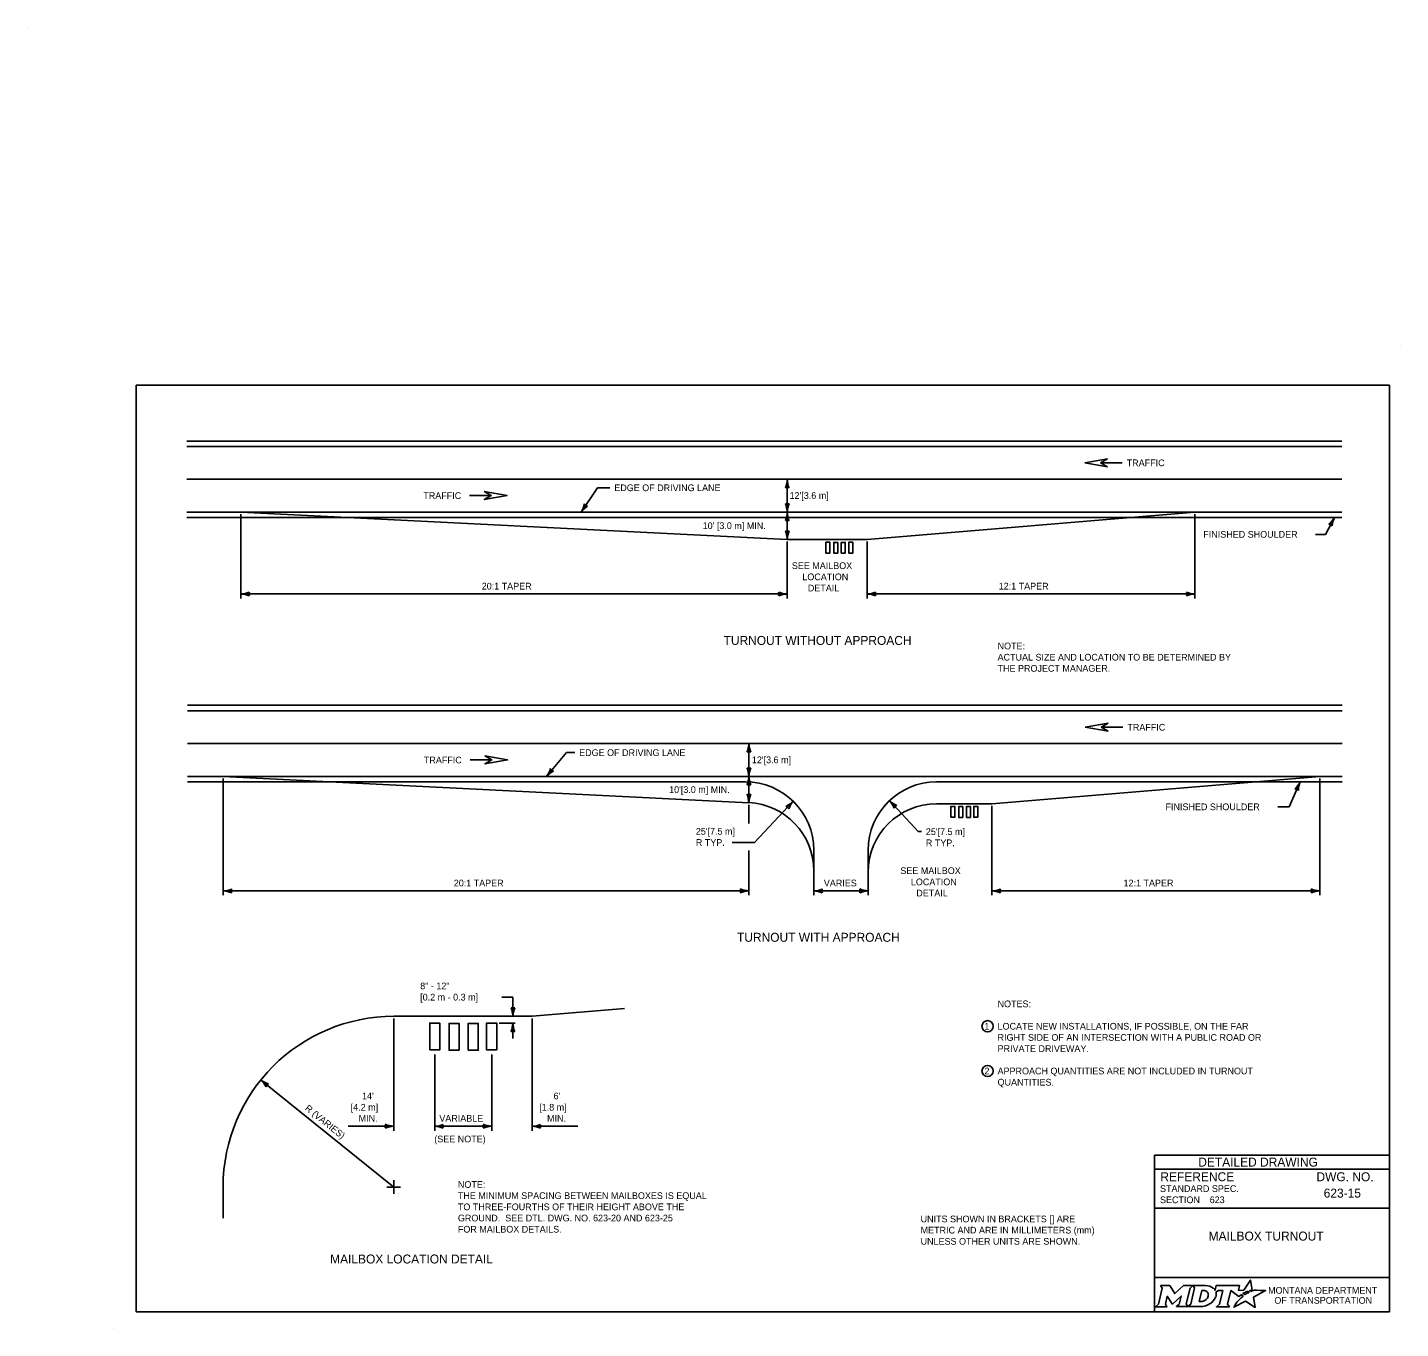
# Model space of a CAD drawing. Extents: x 49991.4 to 50021, y 49987.6 to 50011.4.
# Drawn here: x 50008.76 to 50021.04, y 49999.74 to 50011.36 of the extents above; entities that cross this region are included whole.
import ezdxf

# ---------------------------------------------------------------- set-up
doc = ezdxf.new("R2010")
doc.units = 0
for name, color, linetype in [('Default', 7, 'Continuous'), ('Level 1', 7, 'Continuous'), ('Level 2', 7, 'Continuous'), ('Level 3', 7, 'Continuous'), ('Level 4', 7, 'Continuous'), ('Level 5', 7, 'Continuous')]:
    doc.layers.add(name, color=color, linetype=linetype)

msp = doc.modelspace()

# ---------------------------------------------------------------- linework, layer by layer
at = {"layer": 'Default'}
for points in [[(50018.893, 50000.121), (50018.907, 50000.097), (50018.874, 49999.954), (50018.848, 49999.931), (50018.95, 49999.931), (50018.936, 49999.954), (50018.952, 50000.024), (50018.996, 49999.955), (50019.002, 49999.955), (50019.077, 50000.025), (50019.06, 49999.954), (50019.035, 49999.932), (50019.137, 49999.932), (50019.123, 49999.955), (50019.156, 50000.097)], [(50019.156, 50000.097), (50019.182, 50000.121), (50019.099, 50000.121), (50019.02, 50000.048), (50018.975, 50000.12), (50018.893, 50000.121)], [(50019.295, 50000.121), (50019.182, 50000.121), (50019.196, 50000.098), (50019.163, 49999.954), (50019.137, 49999.932), (50019.248, 49999.932)], [(50019.7, 50000.068), (50019.69, 50000.074), (50019.702, 50000.076), (50019.713, 50000.078), (50019.696, 50000.168), (50019.636, 50000.077), (50019.589, 50000.076), (50019.599, 50000.12), (50019.39, 50000.121), (50019.38, 50000.078), (50019.374, 50000.086)], [(50019.319, 50000.034), (50019.318, 50000.026), (50019.315, 50000.017), (50019.311, 50000.008), (50019.305, 50000.001), (50019.299, 49999.994), (50019.291, 49999.988), (50019.282, 49999.983), (50019.273, 49999.979), (50019.264, 49999.977), (50019.255, 49999.976), (50019.239, 49999.976), (50019.263, 50000.076), (50019.279, 50000.076), (50019.286, 50000.075), (50019.294, 50000.073), (50019.301, 50000.07), (50019.307, 50000.066), (50019.311, 50000.061), (50019.315, 50000.055), (50019.318, 50000.049), (50019.319, 50000.042), (50019.32, 50000.038), (50019.319, 50000.034)], [(50019.387, 50000.062), (50019.411, 50000.075), (50019.448, 50000.075), (50019.42, 49999.954), (50019.392, 49999.931), (50019.508, 49999.931), (50019.491, 49999.954), (50019.52, 50000.075), (50019.591, 50000.023), (50019.612, 50000.038), (50019.632, 50000.027)], [(50019.576, 49999.971), (50019.561, 49999.947), (50019.556, 49999.939), (50019.55, 49999.931), (50019.548, 49999.926), (50019.653, 49999.979), (50019.737, 49999.924), (50019.724, 50000.017), (50019.831, 50000.075), (50019.782, 50000.076), (50019.751, 50000.077), (50019.731, 50000.077), (50019.724, 50000.075), (50019.719, 50000.074), (50019.711, 50000.072), (50019.7, 50000.068)], [(50019.59, 49999.987), (50019.59, 49999.987)], [(50019.65, 50000.04), (50019.648, 50000.039), (50019.629, 50000.048), (50019.639, 50000.054), (50019.644, 50000.056), (50019.652, 50000.06), (50019.658, 50000.063), (50019.666, 50000.066), (50019.673, 50000.068), (50019.685, 50000.061), (50019.681, 50000.059), (50019.676, 50000.056), (50019.672, 50000.054), (50019.667, 50000.051), (50019.665, 50000.05), (50019.662, 50000.049), (50019.66, 50000.047), (50019.658, 50000.046), (50019.655, 50000.044), (50019.652, 50000.042), (50019.65, 50000.04)], [(50019.293, 49999.939), (50019.302, 49999.942), (50019.315, 49999.947), (50019.335, 49999.958)]]:
    msp.add_lwpolyline(points, dxfattribs=at)
for centre, radius, start, end in [((50019.274, 50000.059), 0.118, 300.9103, 339.1383), ((50019.319, 50000.042), 0.0709, 339.5329, 15.8582)]:
    msp.add_arc(centre, radius, start, end, dxfattribs=at)
for centre, major_axis, ratio, start_param, end_param in [((50019.293, 50000.073), (0.0834, -0.0037), 0.568097, 0.61298, 1.570796), ((50019.349, 50000.081), (0.0361, -0.0295), 0.469099, 1.225588, 1.570796), ((50019.583, 49999.979), (-0.00694, -0.00806), 0.008222, 0, 3.137361), ((50019.6, 49999.997), (-0.0098, -0.0102), 0.016458, 3.141593, 6.279097), ((50019.621, 50000.017), (-0.0112, -0.0097), 0.021651, 3.157348, 6.283185), ((50019.248, 50000.08), (0, 0.148), 0.987302, 3.139398, 3.456847)]:
    msp.add_ellipse(centre, major_axis=major_axis, ratio=ratio, start_param=start_param, end_param=end_param, dxfattribs=at)
at = {"layer": 'Level 1'}
for p, q in [((50008.765, 50011.363), (50008.765, 50011.363)), ((50021.038, 50008.524), (50021.038, 50008.524)), ((50020.512, 50007.618), (50010.189, 50007.618)), ((50020.512, 50007.032), (50010.189, 50007.032)), ((50010.671, 50007.032), (50015.556, 50006.788)), ((50016.269, 50006.788), (50019.2, 50007.032)), ((50015.556, 50006.788), (50016.269, 50006.788)), ((50020.517, 50005.256), (50010.194, 50005.256)), ((50020.517, 50004.67), (50010.194, 50004.67)), ((50010.514, 50004.67), (50015.213, 50004.435)), ((50017.385, 50004.426), (50020.316, 50004.67)), ((50016.891, 50004.426), (50017.385, 50004.426)), ((50015.793, 50003.825), (50015.793, 50003.607)), ((50016.28, 50003.607), (50016.28, 50003.815)), ((50013.275, 50002.527), (50014.102, 50002.595)), ((50012.039, 50002.527), (50013.275, 50002.527)), ((50010.513, 50000.723), (50010.513, 50001)), ((50009.537, 49999.736), (50009.537, 49999.736))]:
    msp.add_line(p, q, dxfattribs=at)
for points in [[(50020.938, 50008.165), (50009.737, 50008.165), (50009.737, 49999.886), (50020.938, 49999.886)], [(50015.901, 50006.666), (50015.937, 50006.666), (50015.937, 50006.763), (50015.901, 50006.763)], [(50016.007, 50006.665), (50015.971, 50006.665), (50015.971, 50006.761), (50016.007, 50006.761)], [(50016.039, 50006.665), (50016.075, 50006.665), (50016.075, 50006.761), (50016.039, 50006.761)], [(50016.141, 50006.666), (50016.105, 50006.666), (50016.105, 50006.762), (50016.141, 50006.762)], [(50017.019, 50004.305), (50017.055, 50004.305), (50017.055, 50004.401), (50017.019, 50004.401)], [(50017.125, 50004.304), (50017.089, 50004.304), (50017.089, 50004.4), (50017.125, 50004.4)], [(50017.157, 50004.304), (50017.193, 50004.304), (50017.193, 50004.4), (50017.157, 50004.4)], [(50017.259, 50004.305), (50017.223, 50004.305), (50017.223, 50004.401), (50017.259, 50004.401)], [(50012.36, 50002.226), (50012.45, 50002.226), (50012.45, 50002.466), (50012.36, 50002.466)], [(50012.623, 50002.222), (50012.533, 50002.222), (50012.533, 50002.463), (50012.623, 50002.463)], [(50012.704, 50002.222), (50012.794, 50002.222), (50012.794, 50002.463), (50012.704, 50002.463)], [(50012.959, 50002.225), (50012.869, 50002.225), (50012.869, 50002.466), (50012.959, 50002.466)]]:
    msp.add_lwpolyline(points, close=True, dxfattribs=at)
for centre, radius, start, end in [((50015.182, 50003.825), 0.611, 0, 87.1377), ((50016.891, 50003.815), 0.611, 90, 180), ((50012.039, 50001), 1.526, 90, 180)]:
    msp.add_arc(centre, radius, start, end, dxfattribs=at)
at = {"layer": 'Level 2'}
for centre in [(50017.346, 50002.437), (50017.346, 50002.037)]:
    msp.add_circle(centre, 0.05, dxfattribs=at)
at = {"layer": 'Level 3'}
for p, q in [((50018.419, 50007.507), (50018.215, 50007.471)), ((50018.215, 50007.471), (50018.419, 50007.435)), ((50018.356, 50007.471), (50018.419, 50007.507)), ((50018.551, 50007.471), (50018.356, 50007.471)), ((50018.551, 50007.471), (50018.356, 50007.471)), ((50018.419, 50007.435), (50018.356, 50007.471)), ((50013.86, 50007.249), (50013.715, 50007.032)), ((50013.97, 50007.249), (50013.86, 50007.249)), ((50015.556, 50007.032), (50015.556, 50007.325)), ((50012.715, 50007.18), (50012.91, 50007.18)), ((50012.715, 50007.18), (50012.91, 50007.18)), ((50010.671, 50007.014), (50010.671, 50006.26)), ((50015.556, 50006.788), (50015.556, 50007.032)), ((50019.2, 50007.014), (50019.2, 50006.26)), ((50020.366, 50006.833), (50020.448, 50006.983)), ((50015.556, 50006.77), (50015.556, 50006.26)), ((50016.269, 50006.77), (50016.269, 50006.26)), ((50020.366, 50006.833), (50020.279, 50006.833)), ((50015.556, 50006.3), (50010.671, 50006.3)), ((50016.269, 50006.3), (50019.2, 50006.3)), ((50018.424, 50005.145), (50018.22, 50005.109)), ((50018.361, 50005.109), (50018.424, 50005.145)), ((50018.22, 50005.109), (50018.424, 50005.073)), ((50018.556, 50005.109), (50018.361, 50005.109)), ((50018.556, 50005.109), (50018.361, 50005.109)), ((50018.424, 50005.073), (50018.361, 50005.109)), ((50013.582, 50004.882), (50013.404, 50004.67)), ((50013.656, 50004.882), (50013.582, 50004.882)), ((50015.213, 50004.963), (50015.213, 50004.67)), ((50012.721, 50004.817), (50012.915, 50004.817)), ((50012.721, 50004.817), (50012.915, 50004.817)), ((50010.514, 50004.651), (50010.514, 50003.607)), ((50015.213, 50004.435), (50015.213, 50004.67)), ((50020.316, 50004.651), (50020.316, 50003.607)), ((50020.043, 50004.398), (50020.14, 50004.621)), ((50015.213, 50004.416), (50015.213, 50004.249)), ((50015.608, 50004.448), (50015.263, 50004.079)), ((50016.471, 50004.454), (50016.727, 50004.176)), ((50017.385, 50004.407), (50017.385, 50003.607)), ((50019.941, 50004.398), (50020.043, 50004.398)), ((50016.727, 50004.176), (50016.755, 50004.176)), ((50015.263, 50004.079), (50015.064, 50004.079)), ((50015.213, 50004.009), (50015.213, 50003.607)), ((50015.213, 50003.647), (50010.514, 50003.647)), ((50015.793, 50003.647), (50016.28, 50003.647)), ((50020.316, 50003.647), (50017.385, 50003.647)), ((50013.104, 50002.697), (50013.006, 50002.697)), ((50013.104, 50002.697), (50013.104, 50002.527)), ((50012.039, 50002.506), (50012.039, 50001.503)), ((50012.98, 50002.466), (50013.124, 50002.466)), ((50013.104, 50002.329), (50013.104, 50002.466)), ((50013.275, 50002.506), (50013.275, 50001.503)), ((50010.849, 50001.957), (50012.039, 50001)), ((50012.039, 50001.543), (50011.63, 50001.543)), ((50012.405, 50001.543), (50012.914, 50001.543)), ((50013.275, 50001.543), (50013.683, 50001.543)), ((50011.978, 50001), (50012.1, 50001)), ((50012.039, 50000.939), (50012.039, 50001.061))]:
    msp.add_line(p, q, dxfattribs=at)
for points in [[(50012.848, 50007.216), (50013.051, 50007.18), (50012.848, 50007.144), (50012.91, 50007.18)], [(50012.853, 50004.853), (50013.056, 50004.817), (50012.853, 50004.781), (50012.915, 50004.817)]]:
    msp.add_lwpolyline(points, close=True, dxfattribs=at)
for centre, radius, start, end in [((50015.334, 50007.334), 0.222, 337.456, 357.6395), ((50015.556, 50007.197), 0.0548, 72.1388, 107.8612), ((50015.788, 50007.337), 0.233, 182.8273, 202.0772), ((50013.515, 50007.152), 0.233, 329.0458, 348.2956), ((50013.786, 50007.139), 0.0548, 218.3573, 254.0796), ((50015.556, 50007.161), 0.0548, 252.1388, 287.8612), ((50015.323, 50007.021), 0.233, 2.8273, 22.0772), ((50015.778, 50007.023), 0.222, 157.456, 177.6395), ((50013.894, 50006.901), 0.222, 123.6745, 143.858), ((50015.334, 50007.041), 0.222, 337.456, 357.6395), ((50015.788, 50007.044), 0.233, 182.8273, 202.0772), ((50020.257, 50007.097), 0.222, 308.9444, 329.1279), ((50020.658, 50006.882), 0.233, 154.3157, 173.5656), ((50015.556, 50006.904), 0.0548, 72.1388, 107.8612), ((50015.556, 50006.916), 0.0548, 252.1388, 287.8612), ((50015.323, 50006.777), 0.233, 2.8273, 22.0772), ((50015.778, 50006.779), 0.222, 157.456, 177.6395), ((50020.387, 50006.87), 0.0548, 43.6272, 79.3496), ((50010.66, 50006.532), 0.233, 272.8273, 292.0772), ((50010.662, 50006.078), 0.222, 67.456, 87.6395), ((50010.8, 50006.3), 0.0548, 162.1388, 197.8612), ((50015.565, 50006.522), 0.222, 247.456, 267.6395), ((50015.427, 50006.3), 0.0548, 342.1388, 17.8612), ((50015.567, 50006.067), 0.233, 92.8273, 112.0772), ((50016.258, 50006.532), 0.233, 272.8273, 292.0772), ((50016.26, 50006.078), 0.222, 67.456, 87.6395), ((50016.398, 50006.3), 0.0548, 162.1388, 197.8612), ((50019.209, 50006.522), 0.222, 247.456, 267.6395), ((50019.072, 50006.3), 0.0548, 342.1388, 17.8612), ((50019.211, 50006.067), 0.233, 92.8273, 112.0772), ((50014.991, 50004.972), 0.222, 337.456, 357.6395), ((50015.213, 50004.835), 0.0548, 72.1388, 107.8612), ((50015.446, 50004.974), 0.233, 182.8273, 202.0772), ((50013.218, 50004.811), 0.233, 322.7945, 342.0444), ((50013.568, 50004.52), 0.222, 117.4232, 137.6067), ((50013.486, 50004.768), 0.0548, 212.106, 247.8284), ((50015.213, 50004.798), 0.0548, 252.1388, 287.8612), ((50014.98, 50004.658), 0.233, 2.8273, 22.0772), ((50014.991, 50004.679), 0.222, 337.456, 357.6395), ((50015.435, 50004.661), 0.222, 157.456, 177.6395), ((50015.446, 50004.681), 0.233, 182.8273, 202.0772), ((50015.213, 50004.541), 0.0548, 72.1388, 107.8612), ((50015.213, 50004.563), 0.0548, 252.1388, 287.8612), ((50014.98, 50004.423), 0.233, 2.8273, 22.0772), ((50015.435, 50004.426), 0.222, 157.456, 177.6395), ((50019.94, 50004.718), 0.222, 313.9331, 334.1166), ((50020.089, 50004.503), 0.0548, 48.6159, 84.3382), ((50020.358, 50004.539), 0.233, 159.3044, 178.5542), ((50015.446, 50004.601), 0.222, 296.4506, 316.6341), ((50015.523, 50004.352), 0.0548, 31.1334, 66.8558), ((50015.791, 50004.304), 0.233, 141.8219, 161.0717), ((50016.303, 50004.307), 0.222, 20.9508, 41.1343), ((50016.632, 50004.622), 0.233, 226.3221, 245.5719), ((50016.559, 50004.361), 0.0548, 115.6336, 151.356), ((50010.503, 50003.879), 0.233, 272.8273, 292.0772), ((50010.642, 50003.647), 0.0548, 162.1388, 197.8612), ((50015.222, 50003.869), 0.222, 247.456, 267.6395), ((50015.085, 50003.647), 0.0548, 342.1388, 17.8612), ((50015.781, 50003.879), 0.233, 272.8273, 292.0772), ((50015.921, 50003.647), 0.0548, 162.1388, 197.8612), ((50016.289, 50003.869), 0.222, 247.456, 267.6395), ((50016.152, 50003.647), 0.0548, 342.1388, 17.8612), ((50017.374, 50003.879), 0.233, 272.8273, 292.0772), ((50017.513, 50003.647), 0.0548, 162.1388, 197.8612), ((50020.325, 50003.869), 0.222, 247.456, 267.6395), ((50020.188, 50003.647), 0.0548, 342.1388, 17.8612), ((50010.505, 50003.424), 0.222, 67.456, 87.6395), ((50015.224, 50003.414), 0.233, 92.8273, 112.0772), ((50015.784, 50003.424), 0.222, 67.456, 87.6395), ((50016.292, 50003.414), 0.233, 92.8273, 112.0772), ((50017.376, 50003.424), 0.222, 67.456, 87.6395), ((50020.327, 50003.414), 0.233, 92.8273, 112.0772), ((50013.104, 50002.655), 0.0548, 252.1388, 287.8612), ((50012.871, 50002.515), 0.233, 2.8273, 22.0772), ((50013.326, 50002.517), 0.222, 157.456, 177.6395), ((50012.881, 50002.475), 0.222, 337.456, 357.6395), ((50013.336, 50002.477), 0.233, 182.8273, 202.0772), ((50013.104, 50002.337), 0.0548, 72.1388, 107.8612), ((50010.703, 50001.789), 0.222, 28.6526, 48.8361), ((50010.986, 50002.145), 0.233, 234.0239, 253.2737), ((50010.949, 50001.876), 0.0548, 123.3354, 159.0577), ((50012.048, 50001.766), 0.222, 247.456, 267.6395), ((50011.911, 50001.543), 0.0548, 342.1388, 17.8612), ((50012.05, 50001.311), 0.233, 92.8273, 112.0772), ((50012.394, 50001.776), 0.233, 272.8273, 292.0772), ((50012.396, 50001.321), 0.222, 67.456, 87.6395), ((50012.533, 50001.543), 0.0548, 162.1388, 197.8612), ((50012.923, 50001.766), 0.222, 247.456, 267.6395), ((50012.786, 50001.543), 0.0548, 342.1388, 17.8612), ((50012.926, 50001.311), 0.233, 92.8273, 112.0772), ((50013.264, 50001.776), 0.233, 272.8273, 292.0772), ((50013.266, 50001.321), 0.222, 67.456, 87.6395), ((50013.403, 50001.543), 0.0548, 162.1388, 197.8612)]:
    msp.add_arc(centre, radius, start, end, dxfattribs=at)
at = {"layer": 'Level 4'}
for p, q in [((50010.189, 50007.667), (50020.512, 50007.667)), ((50020.512, 50006.984), (50010.189, 50006.984)), ((50010.194, 50005.305), (50020.517, 50005.305)), ((50010.194, 50004.621), (50015.182, 50004.621)), ((50016.891, 50004.621), (50020.517, 50004.621)), ((50015.793, 50003.825), (50015.793, 50004.01)), ((50016.28, 50004.01), (50016.28, 50003.815)), ((50020.938, 50001.286), (50018.838, 50001.286)), ((50018.838, 50001.286), (50018.838, 49999.886)), ((50020.938, 50001.161), (50018.838, 50001.161)), ((50019.332, 50000.886), (50019.332, 50000.886)), ((50020.574, 50000.946), (50020.574, 50000.946)), ((50020.938, 50000.811), (50018.838, 50000.811)), ((50019.888, 50000.562), (50019.888, 50000.562)), ((50020.938, 50000.193), (50018.838, 50000.193))]:
    msp.add_line(p, q, dxfattribs=at)
for centre, start, end in [((50015.182, 50004.01), 0, 90), ((50016.891, 50004.01), 90, 180)]:
    msp.add_arc(centre, 0.611, start, end, dxfattribs=at)
at = {"layer": 'Level 5'}
for p, q in [((50010.189, 50007.325), (50012.066, 50007.325)), ((50012.066, 50007.325), (50020.512, 50007.325)), ((50010.194, 50004.963), (50012.073, 50004.963)), ((50012.073, 50004.963), (50020.517, 50004.963)), ((50012.405, 50002.186), (50012.405, 50001.503)), ((50012.914, 50002.185), (50012.914, 50001.503))]:
    msp.add_line(p, q, dxfattribs=at)

# ---------------------------------------------------------------- texts
at = {"layer": 'Default'}
for s, p in [('MONTANA DEPARTMENT', (50019.854, 50000.047)), ('OF TRANSPORTATION', (50019.91, 49999.957))]:
    msp.add_text(s, height=0.06, dxfattribs=at).set_placement(p)
at = {"layer": 'Level 2'}
for s, height, p in [('TRAFFIC', 0.06, (50018.59, 50007.442)), ('EDGE OF DRIVING LANE', 0.06, (50014.01, 50007.219)), ("12'[3.6 m]", 0.06, (50015.577, 50007.15)), ('TRAFFIC', 0.06, (50012.303, 50007.149)), ("10' [3.0 m] MIN.", 0.06, (50014.8, 50006.88)), ('FINISHED SHOULDER', 0.06, (50019.275, 50006.803)), ('SEE MAILBOX', 0.06, (50015.597, 50006.523)), ('LOCATION', 0.06, (50015.691, 50006.423)), ('20:1 TAPER', 0.06, (50012.825, 50006.34)), ('DETAIL', 0.06, (50015.74, 50006.323)), ('12:1 TAPER', 0.06, (50017.446, 50006.34)), ('TURNOUT WITHOUT APPROACH', 0.0799, (50014.987, 50005.845)), ('NOTE:', 0.06, (50017.436, 50005.805)), ('ACTUAL SIZE AND LOCATION TO BE DETERMINED BY', 0.06, (50017.436, 50005.705)), ('THE PROJECT MANAGER.', 0.06, (50017.436, 50005.605)), ('TRAFFIC', 0.06, (50018.596, 50005.079)), ('EDGE OF DRIVING LANE', 0.06, (50013.696, 50004.852)), ('TRAFFIC', 0.06, (50012.308, 50004.786)), ("12'[3.6 m]", 0.06, (50015.24, 50004.788)), ("10'[3.0 m] MIN.", 0.06, (50014.5, 50004.522)), ('FINISHED SHOULDER', 0.06, (50018.937, 50004.368)), ("25'[7.5 m] ", 0.06, (50014.739, 50004.149)), ("25'[7.5 m]", 0.06, (50016.795, 50004.146)), ('R TYP.', 0.06, (50014.739, 50004.049)), ('R TYP.', 0.06, (50016.795, 50004.046)), ('SEE MAILBOX', 0.06, (50016.567, 50003.797)), ('20:1 TAPER', 0.06, (50012.575, 50003.687)), ('VARIES', 0.06, (50015.883, 50003.687)), ('LOCATION', 0.06, (50016.661, 50003.697)), ('DETAIL', 0.06, (50016.71, 50003.597)), ('12:1 TAPER', 0.06, (50018.562, 50003.687)), ('TURNOUT WITH APPROACH', 0.0799, (50015.107, 50003.192)), ('8" - 12"', 0.06, (50012.275, 50002.767)), ('[0.2 m - 0.3 m]', 0.06, (50012.275, 50002.667)), ('NOTES:', 0.06, (50017.436, 50002.607)), ('1', 0.06, (50017.318, 50002.406)), ('LOCATE NEW INSTALLATIONS, IF POSSIBLE, ON THE FAR', 0.06, (50017.436, 50002.407)), ('RIGHT SIDE OF AN INTERSECTION WITH A PUBLIC ROAD OR', 0.06, (50017.436, 50002.307)), ('PRIVATE DRIVEWAY.', 0.06, (50017.436, 50002.207)), ('2', 0.06, (50017.319, 50002.007)), ('APPROACH QUANTITIES ARE NOT INCLUDED IN TURNOUT', 0.06, (50017.436, 50002.007)), ('QUANTITIES.', 0.06, (50017.436, 50001.907)), ("14'", 0.06, (50011.755, 50001.784)), ("6'", 0.06, (50013.467, 50001.784)), ('[4.2 m]', 0.06, (50011.654, 50001.683)), ('[1.8 m]', 0.06, (50013.339, 50001.683)), ('MIN.', 0.06, (50011.725, 50001.584)), ('VARIABLE', 0.06, (50012.446, 50001.584)), ('MIN.', 0.06, (50013.409, 50001.584)), ('(SEE NOTE)', 0.06, (50012.401, 50001.399)), ('THE MINIMUM SPACING BETWEEN MAILBOXES IS EQUAL ', 0.06, (50012.612, 50000.893)), ('NOTE:', 0.06, (50012.612, 50000.993)), ('623-15', 0.08, (50020.351, 50000.906)), ('TO THREE-FOURTHS OF THEIR HEIGHT ABOVE THE ', 0.06, (50012.612, 50000.793)), ('623', 0.06, (50019.332, 50000.856)), ('GROUND.  SEE DTL. DWG. NO. 623-20 AND 623-25 ', 0.06, (50012.612, 50000.693)), ('UNITS SHOWN IN BRACKETS [] ARE ', 0.06, (50016.748, 50000.685)), ('FOR MAILBOX DETAILS.', 0.06, (50012.612, 50000.593)), ('METRIC AND ARE IN MILLIMETERS (mm) ', 0.06, (50016.748, 50000.585)), ('MAILBOX TURNOUT', 0.08, (50019.322, 50000.522)), ('UNLESS OTHER UNITS ARE SHOWN.', 0.06, (50016.748, 50000.485)), ('MAILBOX LOCATION DETAIL', 0.0799, (50011.47, 50000.317))]:
    msp.add_text(s, height=height, dxfattribs=at).set_placement(p)
msp.add_text('R (VARIES)', height=0.06, rotation=321.1961, dxfattribs=at).set_placement((50011.24, 50001.694))
at = {"layer": 'Level 4'}
for s, height, p in [('DETAILED DRAWING', 0.0799, (50019.23, 50001.183)), ('REFERENCE', 0.08, (50018.891, 50001.052)), ('DWG. NO.', 0.08, (50020.286, 50001.052)), ('STANDARD SPEC.', 0.06, (50018.888, 50000.956)), ('SECTION', 0.06, (50018.888, 50000.856))]:
    msp.add_text(s, height=height, dxfattribs=at).set_placement(p)

doc.saveas('drawing.dxf')
